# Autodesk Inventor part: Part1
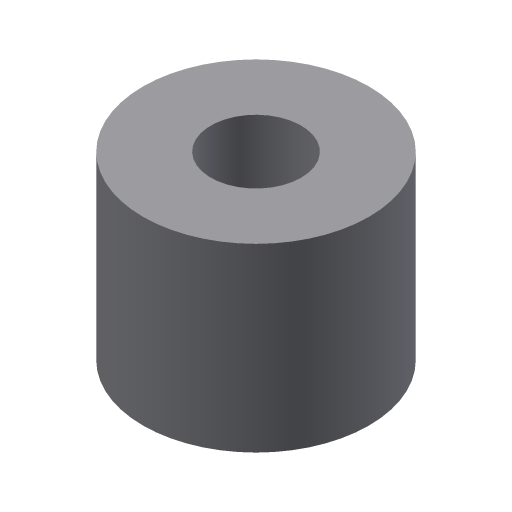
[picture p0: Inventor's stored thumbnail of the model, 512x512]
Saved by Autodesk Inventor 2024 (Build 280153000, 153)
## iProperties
Shininess: 77.0
Angle Display Precision: 2
Document Length Units: 11269
Document Angle Units: 11279
Document Time Units: 11290
Document Mass Units: 11283
Document Length Units Precision: 3
Document Angle Units Precision: 2
Created: 2002-01
Part Number: Part1
Document SubType Name: Modeling
Designer: ***
Density: 1 g/cm^3
Material: Generic
Appearance: Default
Density: 0.0
Volumn: 0.0
Area: 0.0
PropertySet Name: Model Information
Control State: 0
Master: False
Checked Out: False
Author: ***
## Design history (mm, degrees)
sketch "Sketch1"
  geometry: C1 r 25 at (0, 0); C2 r 10 at (0, 0)
  constraints: 2 centre point, 1 coincident
  dimensions: "d0" = 50 diameter of C1; "d1" = 20 diameter of C2
extrude "Extrusion1" new body sketch "Sketch1" distance "d2" = 40; taper "d3" = 0 deg
body "Solid1"
